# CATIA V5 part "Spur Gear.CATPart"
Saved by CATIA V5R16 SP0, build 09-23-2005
Part number: Spur Gear
Bounding box of the stored display mesh (mm): x 0 to 23, y -51.943 to 51.943, z -51.993 to 51.993
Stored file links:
  C:\V5_education\CATIA Data\ASD\Power Transmission Gear Assembly\Assembly Data\Spur Gear.CATPart
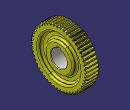
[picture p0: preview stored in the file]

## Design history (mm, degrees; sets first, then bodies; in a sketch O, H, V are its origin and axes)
External parameters (linked from other documents)
  External.m = 2 mm
  External.a = 20 deg
  External.Z = 50
  External.rp = 50 mm {= External.m * External.Z /2}
  External.ra = 52 mm {= External.rp + External.m}
  External.rb = 46.9846 mm {= External.rp * cos(External.a )}
  External.rf = 47.5 mm {= External.rp -1.25*External.m}
  External.rc = 0.76 mm {= External.m * 0.38}
  External.c = 0.115855 {= sqrt (1/(cos(External.a )*cos(External.a )) -1) / PI}
Set1 "Reference Data"
  Point1 "Original Point": (0, 0, 0)
  Point2: (0, 0, 46.9846)
  Point3: (0, 0.4808, 49.2463)
  Point4: (0, 3.7336, 55.3636)
  Point5: (0, 11.9831, 63.4417)
  Point6: (0, 26.4399, 70.6719)
  Curve1: Elements (Point2; Point3; Point4; Point5; Point6)
  Extrapol1: ToExtrapol Point2, Support Curve1, Length 4 {= External.m *2}
  Point7: (0, 0.7452, 49.9944)
  Circle1: type CtrRad, Start 0, End 180, Center Point1, Support yz-plane, Radius 47.5 {= External.rf}, FirstDirection (0, 1, 0)
  Rotate1: ToTransfor Extrapol1, Axis X axis, Angle 2.654
  Circle2: type CtrRad, Start 0, End 180, Center Point1, Support yz-plane, Radius 52 {= External.ra}, FirstDirection (0, 1, 0)
  Corner1: Element1 Rotate1, Element2 Circle1, Radius 0.76 {= External.rc}
  Plane1: type Angle, RefPlane zx-plane, Direction X axis, Angle 3.6 {= 180deg/External.Z}
  Symmetry1: ToTransfor Corner1, Reference Plane1
  Split1: ToCut Rotate1, Cutting (Corner1; Circle2)
  Symmetry2: ToTransfor Split1, Reference zx-plane
  Trim1: Trimmed (Symmetry2; Circle2; Split1; Corner1; Circle1; Symmetry1)
  CircPattern1: of Trim1, instances 50 {= External.Z}, angular step 7.2 {= 360.0*1 deg/CircPattern1.AngularNumber}, axis from X axis
  Join1: Elements (Trim1; CircPattern1)
  Plane2: type Offset, RefPlane yz-plane, Offset 11.5
Body1 (main body)
  Pad1: profile Join1, length 23
  Sketch1 on zx-plane, origin (0, 0, 0), H (-1, 0, 0), V (0, 0, 1)
    construction line L1 (-11.5, 0) -> (-11.5, 51.894)
    point P1 (-11.5, 0)
    line L2 (0, 0) -> (0, 49.8787)
    line L3 (-2.1213, 52) -> (-20.8787, 52)
    line L4 (-23, 49.8787) -> (-23, 0)
    point P3 (-23, 0)
    line L5 (-20.8787, 52) -> (-23, 49.8787)
    line L6 (0, 49.8787) -> (-2.1213, 52)
    axis line L7 (-23, 0) -> (0, 0)
    line L8 (-23, 0) -> (0, 0)
    distance L1 V = 11.5
    distance L3 H = 52
    angle L3 L5 = 45
    length L5 = 3
    angle L2 L6 = 45 {= Sketch1.angle(L3 L5)}
    length L6 = 3 {= Sketch1.length(L5)}
    coincidence: P1 H, P3 H
    vertical: L1 V, L2 V, L4 V
    horizontal: L3 H, L7 H, L8 H
    symmetry: L4 L2 L1
  Groove1: profile Sketch1, axis Sketch1.L7, angle 360
  Body2
    Sketch2 on zx-plane, origin (0, 0, 0), H (-1, 0, 0), V (0, 0, 1)
      point P1 (0, 38)
      line L1 (0, 38) -> (-7, 38)
      line L2 (-7, 38) -> (-7, 26.5)
      line L3 (-7, 26.5) -> (0, 26.5)
      line L4 (0, 26.5) -> (0, 38)
      axis line L5 (0, 0) -> (39.6206, 0)
      distance L3 H = 26.5
      distance H L1 = 38
      distance L4 L2 = 7
      coincidence: P1 V
      horizontal: L1 H, L3 H, L5 H
      vertical: L2 V, L4 V
    Groove2: profile Sketch2, axis Sketch2.L5, angle 360
    Fillet1: radius 3, on face of Groove2 from Sketch2.L2
    Mirror1: of the body so far, about Plane2
  Assemble1: tool Body2
  Fillet2: radius 3, on edge [face of Mirror1 | face of Groove1 from Sketch1.L4]; edge [face of Groove1 from Sketch1.L2 | face of Groove2 from Sketch2.L1]; edge [face of Groove2 from Sketch2.L3 | face of Groove1 from Sketch1.L2]; edge [face of Groove1 from Sketch1.L4 | face of Mirror1]
  Sketch3 on Plane2, origin (11.5, 0, 0), H (0, 1, 0), V (0, 0, 1)
    arc A1 centre (0, 0) radius 15 from (-4, 14.4568) to (4, 14.4568) ccw
    line L1 (-4, 18.3) -> (4, 18.3)
    line L2 (4, 18.3) -> (4, 14.4568)
    line L3 (-4, 14.4568) -> (-4, 18.3)
    distance L2 L3 = 8
    distance L1 A1 = 33.3
    radius A1 = 15
    horizontal: L1 H
    vertical: L2 V, L3 V
    symmetry: L3 L2 V
  Pocket1: profile Sketch3, direction (-1, 0, 0), through (limit type 6), opposite side through (limit type 6)
  Chamfer1: length 1, angle 45, on edge [face of Groove1 from Sketch1.L4 | face of Pocket1 from Sketch3.A1]; edge [face of Pocket1 from Sketch3.A1 | face of Groove1 from Sketch1.L2]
